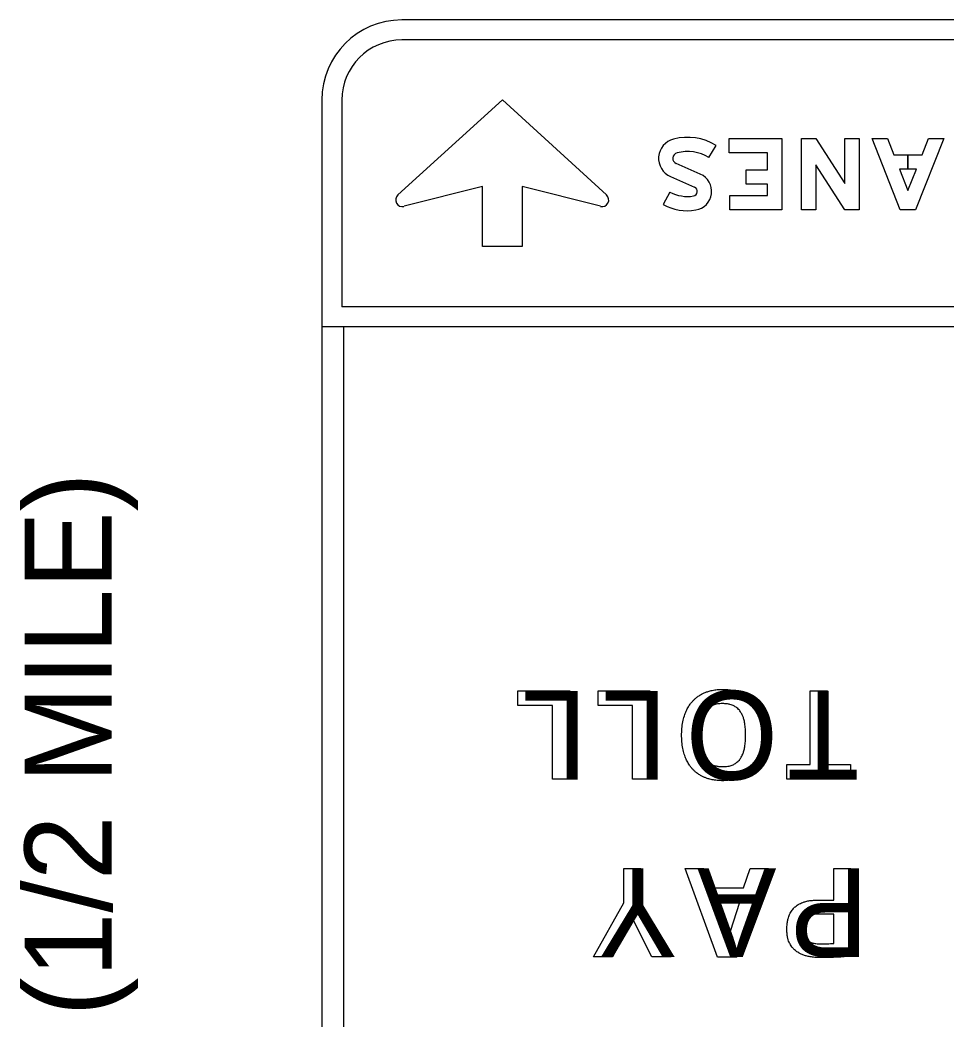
# Model space of a CAD drawing. Extents: x -102643 to -98250, y 54554 to 62384.
# Drawn here: x -102370.7 to -102005.6, y 60279.9 to 60673.7 of the extents above; entities that cross this region are included whole.
import ezdxf

# ---------------------------------------------------------------- set-up
doc = ezdxf.new("R2010")
doc.units = 0
doc.layers.add('SignPanel', color=7, linetype='Continuous')
doc.layers.add('TextLabel', color=7, linetype='Continuous')

msp = doc.modelspace()

# ---------------------------------------------------------------- linework, layer by layer
at = {"layer": 'SignPanel'}
for p, q in [((-101715.38, 60673.71), (-102220.13, 60673.71)), ((-101823.17, 60665.82), (-102220.13, 60665.82)), ((-102251.68, 60642.16), (-102251.68, 60184.73)), ((-102243.79, 60642.16), (-102243.79, 60560.66)), ((-102221.66, 60604.78), (-102180.49, 60642.19)), ((-102180.49, 60642.19), (-102139.39, 60604.78)), ((-102099.08, 60619.49), (-102096.17, 60624.28)), ((-102099.08, 60619.49), (-102096.17, 60624.28)), ((-102099.08, 60619.49), (-102096.17, 60624.28)), ((-102102.44, 60612.95), (-102111.94, 60617.11)), ((-102102.44, 60612.95), (-102111.94, 60617.11)), ((-102102.44, 60612.95), (-102111.94, 60617.11)), ((-102114.19, 60611.97), (-102104.69, 60607.81)), ((-102114.19, 60611.97), (-102104.69, 60607.81)), ((-102114.19, 60611.97), (-102104.69, 60607.81)), ((-102188.38, 60608.09), (-102219.26, 60600.27)), ((-102188.38, 60584.43), (-102188.38, 60608.09)), ((-102141.75, 60600.27), (-102172.64, 60608.09)), ((-102172.64, 60608.09), (-102172.64, 60584.43)), ((-102114.42, 60605.87), (-102117.07, 60600.92)), ((-102114.42, 60605.87), (-102117.07, 60600.92)), ((-102114.42, 60605.87), (-102117.07, 60600.92)), ((-102172.64, 60584.43), (-102188.38, 60584.43)), ((-101823.17, 60560.66), (-102243.79, 60560.66)), ((-101815.28, 60552.78), (-102251.68, 60552.78)), ((-102243.18, 60552.78), (-102243.18, 60184.73))]:
    msp.add_line(p, q, dxfattribs=at)
for points in [[(-102090.84, 60598.92), (-102090.84, 60604.53), (-102075.97, 60604.53), (-102075.97, 60609.02), (-102084.39, 60609.02), (-102084.39, 60614.63), (-102075.97, 60614.63), (-102075.97, 60621.36), (-102091.12, 60621.36), (-102091.12, 60626.97), (-102070.36, 60626.97), (-102070.36, 60598.92)], [(-102090.84, 60598.92), (-102090.84, 60604.53), (-102075.97, 60604.53), (-102075.97, 60609.02), (-102084.39, 60609.02), (-102084.39, 60614.63), (-102075.97, 60614.63), (-102075.97, 60621.36), (-102091.12, 60621.36), (-102091.12, 60626.97), (-102070.36, 60626.97), (-102070.36, 60598.92)], [(-102090.84, 60598.92), (-102090.84, 60604.53), (-102075.97, 60604.53), (-102075.97, 60609.02), (-102084.39, 60609.02), (-102084.39, 60614.63), (-102075.97, 60614.63), (-102075.97, 60621.36), (-102091.12, 60621.36), (-102091.12, 60626.97), (-102070.36, 60626.97), (-102070.36, 60598.92)], [(-102039.79, 60598.92), (-102045.4, 60598.92), (-102056.9, 60616.59), (-102056.9, 60598.92), (-102062.51, 60598.92), (-102062.51, 60626.97), (-102056.96, 60626.97), (-102045.4, 60609.21), (-102045.4, 60626.97), (-102039.79, 60626.97)], [(-102039.79, 60598.92), (-102045.4, 60598.92), (-102056.9, 60616.59), (-102056.9, 60598.92), (-102062.51, 60598.92), (-102062.51, 60626.97), (-102056.96, 60626.97), (-102045.4, 60609.21), (-102045.4, 60626.97), (-102039.79, 60626.97)], [(-102039.79, 60598.92), (-102045.4, 60598.92), (-102056.9, 60616.59), (-102056.9, 60598.92), (-102062.51, 60598.92), (-102062.51, 60626.97), (-102056.96, 60626.97), (-102045.4, 60609.21), (-102045.4, 60626.97), (-102039.79, 60626.97)], [(-102026.14, 60620.52), (-102015.01, 60620.52), (-102012.45, 60626.97), (-102006.41, 60626.97), (-102017.56, 60598.92), (-102023.59, 60598.92), (-102034.74, 60626.97), (-102028.7, 60626.97)], [(-102020.57, 60614.91), (-102020.57, 60620.52), (-102015.01, 60620.52), (-102012.45, 60626.97), (-102006.41, 60626.97), (-102017.56, 60598.92), (-102023.59, 60598.92), (-102034.74, 60626.97), (-102028.7, 60626.97), (-102026.14, 60620.52), (-102020.58, 60620.52), (-102020.58, 60614.91), (-102023.91, 60614.91), (-102020.57, 60606.52), (-102017.24, 60614.91)], [(-102020.57, 60614.91), (-102020.57, 60620.52), (-102015.01, 60620.52), (-102012.45, 60626.97), (-102006.41, 60626.97), (-102017.56, 60598.92), (-102023.59, 60598.92), (-102034.74, 60626.97), (-102028.7, 60626.97), (-102026.14, 60620.52), (-102020.58, 60620.52), (-102020.58, 60614.91), (-102023.91, 60614.91), (-102020.57, 60606.52), (-102017.24, 60614.91)], [(-102017.24, 60614.91), (-102023.91, 60614.91), (-102020.57, 60606.52)]]:
    msp.add_lwpolyline(points, close=True, dxfattribs=at)
for points in [[(-102153.94, 60409.24), (-102153.94, 60374.4), (-102160.72, 60374.4), (-102160.72, 60403.48), (-102174.36, 60403.48), (-102174.36, 60409.24), (-102153.94, 60409.24)], [(-102122.36, 60409.24), (-102122.36, 60374.4), (-102129.13, 60374.4), (-102129.13, 60403.48), (-102142.78, 60403.48), (-102142.78, 60409.24), (-102122.36, 60409.24)], [(-102059.17, 60380.2), (-102059.17, 60409.24), (-102052.35, 60409.24), (-102052.35, 60380.2), (-102043.2, 60380.2), (-102043.2, 60374.4), (-102068.36, 60374.4), (-102068.36, 60380.2), (-102059.17, 60380.2)], [(-102132.66, 60325.66), (-102132.66, 60339.28), (-102125.89, 60339.28), (-102125.89, 60325.87), (-102113.95, 60304.44), (-102121.61, 60304.44), (-102129.34, 60319.81), (-102137.11, 60304.44), (-102144.51, 60304.44), (-102132.66, 60325.66)], [(-102101.11, 60339.28), (-102098.36, 60331.62), (-102085.41, 60331.62), (-102082.74, 60339.28), (-102075.62, 60339.28), (-102088.05, 60304.31), (-102095.71, 60304.31), (-102108.35, 60339.28), (-102101.11, 60339.28)], [(-102056.37, 60326.75), (-102049.82, 60326.75), (-102049.82, 60339.28), (-102043.05, 60339.28), (-102043.05, 60304.7)], [(-102091.92, 60310.83), (-102091.75, 60310.83), (-102086.84, 60326.03), (-102096.83, 60326.03), (-102091.92, 60310.83)], [(-102049.82, 60309.7), (-102049.82, 60321.29), (-102055.05, 60321.29)]]:
    msp.add_lwpolyline(points, dxfattribs=at)
for centre, radius, start, end in [((-102220.13, 60642.16), 31.55, 90, 180), ((-102220.13, 60642.16), 23.66, 90, 180), ((-102111.04, 60619.16), 7.85, 104.4775, 246.3243), ((-102111.04, 60619.16), 7.85, 104.4775, 246.3243), ((-102111.04, 60619.16), 7.85, 104.4775, 246.3243), ((-102107.53, 60605.58), 21.88, 58.7194, 104.4775), ((-102107.53, 60605.58), 21.88, 58.7194, 104.4775), ((-102107.53, 60605.58), 21.88, 58.7194, 104.4775), ((-102111.04, 60619.16), 2.24, 104.4775, 246.3243), ((-102111.04, 60619.16), 2.24, 104.4775, 246.3243), ((-102111.04, 60619.16), 2.24, 104.4775, 246.3243), ((-102107.53, 60605.58), 16.27, 58.7194, 104.4775), ((-102107.53, 60605.58), 16.27, 58.7194, 104.4775), ((-102107.53, 60605.58), 16.27, 58.7194, 104.4775), ((-102105.43, 60606.14), 7.43, 279.4877, 66.3243), ((-102105.43, 60606.14), 7.43, 279.4877, 66.3243), ((-102105.43, 60606.14), 7.43, 279.4877, 66.3243), ((-102107.53, 60618.73), 14.59, 241.8214, 279.4877), ((-102107.53, 60618.73), 14.59, 241.8214, 279.4877), ((-102107.53, 60618.73), 14.59, 241.8214, 279.4877), ((-102105.43, 60606.14), 1.82, 279.4877, 66.3243), ((-102105.43, 60606.14), 1.82, 279.4877, 66.3243), ((-102105.43, 60606.14), 1.82, 279.4877, 66.3243), ((-102219.93, 60602.78), 2.63, 132.2847, 284.1719), ((-102141.17, 60602.78), 2.63, 255.8249, 47.7118), ((-102107.53, 60618.73), 20.2, 241.8214, 279.4877), ((-102107.53, 60618.73), 20.2, 241.8214, 279.4877), ((-102107.53, 60618.73), 20.2, 241.8214, 279.4877)]:
    msp.add_arc(centre, radius, start, end, dxfattribs=at)
for points in [[(-102109.81, 60391.79), (-102109.8, 60392.49), (-102109.76, 60394.48), (-102109.4, 60397.07), (-102108.75, 60399.45), (-102108.04, 60401.32), (-102107.16, 60403.03), (-102106.23, 60404.34), (-102105.55, 60405.13), (-102104.84, 60405.87), (-102103.88, 60406.72), (-102102.6, 60407.6), (-102101.45, 60408.22), (-102100.48, 60408.64), (-102099.45, 60409.02), (-102097.81, 60409.47), (-102095.77, 60409.78), (-102094.28, 60409.82), (-102093.65, 60409.83)], [(-102093.65, 60409.83), (-102093.03, 60409.82), (-102091.53, 60409.78), (-102089.49, 60409.47), (-102087.84, 60409.01), (-102086.81, 60408.64), (-102085.83, 60408.22), (-102084.68, 60407.6), (-102083.39, 60406.72), (-102082.42, 60405.87), (-102081.7, 60405.13), (-102081.02, 60404.34), (-102080.25, 60403.26), (-102079.31, 60401.58), (-102078.56, 60399.72), (-102077.84, 60397.07), (-102077.48, 60394.48), (-102077.44, 60392.49), (-102077.43, 60391.79)], [(-102093.66, 60404.24), (-102094.08, 60404.23), (-102094.7, 60404.22), (-102095.69, 60404.1), (-102096.6, 60403.92), (-102097.44, 60403.63), (-102098.06, 60403.34), (-102098.62, 60403.03), (-102099.28, 60402.57), (-102099.98, 60401.92), (-102100.49, 60401.31), (-102100.84, 60400.78), (-102101.18, 60400.2), (-102101.62, 60399.28), (-102102.02, 60398.09), (-102102.38, 60396.42), (-102102.64, 60394.37), (-102102.68, 60392.68), (-102102.7, 60391.8)], [(-102084.58, 60391.8), (-102084.6, 60392.69), (-102084.64, 60394.39), (-102084.9, 60396.45), (-102085.26, 60398.13), (-102085.66, 60399.3), (-102086.11, 60400.23), (-102086.44, 60400.79), (-102086.79, 60401.32), (-102087.3, 60401.93), (-102088, 60402.57), (-102088.66, 60403.03), (-102089.22, 60403.34), (-102089.84, 60403.63), (-102090.69, 60403.92), (-102092.02, 60404.19), (-102093.03, 60404.22), (-102093.66, 60404.24)], [(-102093.65, 60373.85), (-102094.28, 60373.86), (-102095.79, 60373.9), (-102097.84, 60374.21), (-102099.5, 60374.66), (-102100.53, 60375.04), (-102101.51, 60375.46), (-102102.66, 60376.08), (-102103.94, 60376.96), (-102104.9, 60377.8), (-102105.6, 60378.55), (-102106.27, 60379.34), (-102107.19, 60380.65), (-102108.07, 60382.35), (-102108.76, 60384.21), (-102109.4, 60386.57), (-102109.76, 60389.13), (-102109.8, 60391.1), (-102109.81, 60391.79)], [(-102102.7, 60391.8), (-102102.68, 60390.92), (-102102.64, 60389.24), (-102102.38, 60387.18), (-102102.02, 60385.51), (-102101.62, 60384.33), (-102101.18, 60383.41), (-102100.84, 60382.84), (-102100.49, 60382.31), (-102099.98, 60381.7), (-102099.28, 60381.06), (-102098.62, 60380.61), (-102098.06, 60380.29), (-102097.44, 60380), (-102096.59, 60379.72), (-102095.26, 60379.45), (-102094.25, 60379.41), (-102093.62, 60379.39)], [(-102077.43, 60391.79), (-102077.44, 60391.1), (-102077.48, 60389.13), (-102077.83, 60386.57), (-102078.47, 60384.21), (-102078.98, 60382.85), (-102079.56, 60381.59), (-102080.22, 60380.42), (-102080.99, 60379.34), (-102081.67, 60378.55), (-102082.38, 60377.8), (-102083.36, 60376.96), (-102084.64, 60376.08), (-102085.8, 60375.46), (-102086.78, 60375.04), (-102087.81, 60374.66), (-102089.46, 60374.21), (-102091.52, 60373.9), (-102093.03, 60373.86), (-102093.65, 60373.85)], [(-102093.62, 60379.39), (-102093.2, 60379.4), (-102092.57, 60379.42), (-102091.57, 60379.54), (-102090.66, 60379.72), (-102089.82, 60380), (-102089.21, 60380.29), (-102088.65, 60380.61), (-102087.99, 60381.06), (-102087.3, 60381.71), (-102086.79, 60382.31), (-102086.44, 60382.84), (-102086.11, 60383.41), (-102085.66, 60384.33), (-102085.26, 60385.51), (-102084.9, 60387.18), (-102084.64, 60389.24), (-102084.6, 60390.92), (-102084.58, 60391.8)], [(-102068.32, 60315.22), (-102068.31, 60315.65), (-102068.29, 60316.9), (-102068.06, 60318.52), (-102067.71, 60319.86), (-102067.41, 60320.74), (-102067.05, 60321.56), (-102066.51, 60322.48), (-102065.99, 60323.17), (-102065.52, 60323.69), (-102065.02, 60324.18), (-102064.32, 60324.73), (-102063.38, 60325.3), (-102062.53, 60325.7), (-102061.61, 60326.05), (-102060.14, 60326.46), (-102058.31, 60326.72), (-102056.88, 60326.74), (-102056.37, 60326.75)], [(-102055.05, 60321.29), (-102055.52, 60321.28), (-102056.42, 60321.27), (-102057.41, 60321.17), (-102058.11, 60321.05), (-102058.57, 60320.94), (-102059.08, 60320.75), (-102059.47, 60320.54), (-102059.76, 60320.35), (-102060.03, 60320.14), (-102060.34, 60319.82), (-102060.66, 60319.37), (-102060.88, 60318.94), (-102061.03, 60318.56), (-102061.17, 60318.13), (-102061.34, 60317.39), (-102061.45, 60316.43), (-102061.46, 60315.7), (-102061.46, 60315.39)], [(-102054.61, 60304.1), (-102055.07, 60304.11), (-102056.44, 60304.13), (-102058.23, 60304.31), (-102059.95, 60304.61), (-102061.36, 60304.96), (-102062.67, 60305.46), (-102063.7, 60306.02), (-102064.34, 60306.43), (-102064.94, 60306.88), (-102065.64, 60307.51), (-102066.37, 60308.37), (-102066.9, 60309.17), (-102067.27, 60309.85), (-102067.61, 60310.6), (-102067.94, 60311.63), (-102068.26, 60313.24), (-102068.3, 60314.46), (-102068.32, 60315.22)], [(-102061.46, 60315.39), (-102061.46, 60315.12), (-102061.45, 60314.38), (-102061.34, 60313.44), (-102061.15, 60312.7), (-102060.99, 60312.24), (-102060.8, 60311.82), (-102060.51, 60311.36), (-102060.22, 60311.03), (-102059.97, 60310.79), (-102059.68, 60310.57), (-102059.29, 60310.32), (-102058.77, 60310.08), (-102058.29, 60309.92), (-102057.77, 60309.79), (-102056.94, 60309.63), (-102055.9, 60309.53), (-102055.1, 60309.52), (-102054.81, 60309.52)], [(-102054.81, 60309.52), (-102054.41, 60309.52), (-102053.62, 60309.53), (-102052.4, 60309.57), (-102051.13, 60309.63), (-102050.26, 60309.67), (-102049.82, 60309.7)], [(-102043.05, 60304.7), (-102043.88, 60304.62), (-102045.66, 60304.44), (-102048.48, 60304.26), (-102051.5, 60304.13), (-102053.57, 60304.11), (-102054.61, 60304.1)]]:
    msp.add_open_spline(points, degree=3, dxfattribs=at)

# ---------------------------------------------------------------- texts
for s, p in [('L', (-102146.96, 60409.24)), ('L', (-102146.96, 60409.24)), ('L', (-102115.37, 60409.24)), ('L', (-102115.37, 60409.24)), ('O', (-102071.84, 60409.24)), ('O', (-102071.84, 60409.24)), ('T', (-102039.7, 60409.24)), ('T', (-102039.7, 60409.24)), ('Y', (-102111.5, 60339.28)), ('Y', (-102111.5, 60339.28)), ('A', (-102072.49, 60339.28)), ('A', (-102072.49, 60339.28)), ('P', (-102036.06, 60339.28)), ('P', (-102036.06, 60339.28))]:
    msp.add_text(s, height=34.96, rotation=180, dxfattribs=at).set_placement(p)
at = {"layer": 'TextLabel'}
msp.add_text('(1/2 MILE)', height=34.335, rotation=90, dxfattribs=at).set_placement((-102334.51, 60280.99))

doc.saveas('drawing.dxf')
